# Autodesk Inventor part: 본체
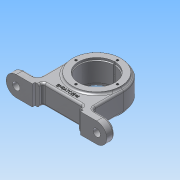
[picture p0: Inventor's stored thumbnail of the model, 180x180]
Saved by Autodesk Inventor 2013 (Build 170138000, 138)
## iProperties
Created: 2019-05
Part Number: 본체
Material: 알루미늄 6061
Document SubType Name: Modeling
Designer: Administrator
Density: 2.71 g/cm^3
Mass: 453.84 g
Surface Area: 319.447 cm^2
Volume: 167.468 cm^3
Author: Administrator
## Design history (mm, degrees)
sketch "스케치3"
  geometry: L1 (40, 4.967)-(40, -37.033); L2 (-40, -37.033)-(-40, 4.967); L3 (75, -43.033)-(75, -55.033); L4 (-75, -55.033)-(-75, -43.033); L5 (-75, -43.033)-(-46, -43.033); L6 (46, -43.033)-(75, -43.033); L7 (36, -51.033)-(36, -55.033); L8 (-36, -55.033)-(-36, -51.033); L9 (75, -55.033)-(36, -55.033); L10 (-36, -55.033)-(-75, -55.033); L11 (-30, -45.033)-(30, -45.033); L12 (30, -45.033)-(30, -51.033); L13 (-30, -51.033)-(-30, -45.033); L14 (-36, -51.033)-(-30, -51.033); L15 (30, -51.033)-(36, -51.033); C1 r 26 at (0, 4.967); A1 r 40 centre (0, 4.967) between (40, 4.967) and (-40, 4.967); A2 r 6 centre (-46, -37.033) between (-46, -43.033) and (-40, -37.033); A3 r 6 centre (46, -37.033) between (40, -37.033) and (46, -43.033); 3 further points
  constraints: 30 end point, 8 parallel, 6 point on circle, 5 horizontal, 5 perpendicular, 4 centre point, 4 tangent, 2 vertical alignment, 1 coincident, 1 equal radius, 1 horizontal alignment
  dimensions: "d12" = 80 diameter of A1; "d16" = 150 distance of L3.end L4.start; "d17" = 12 distance of L3.start L3.end; "d22" = 10 distance between parallel lines of L11 L10; "d23" = 4 distance between parallel lines of L10 L14; "d24" = 60 distance between parallel lines of L13 L12; "d25" = 72 distance between parallel lines of L7 L8; "d26" = 6 radius of A2; "d27" = 52 diameter of C1
extrude "돌출1" new body sketch "스케치3" distance "d28" = 15; taper "d30" = 0 deg; dims "d29" = 15, "d31" = 0
fillet "모깎기1" dims "d32" = 15
sketch "스케치4"
  geometry: C1 r 9 at (-14, 15); A1 r 15 centre (-14, 15) between (-14, 30) and (-14, 0) reference; 1 further point
  constraints: 1 centre point, 1 coincident
  dimensions: "d33" = 18 diameter of C1
extrude "돌출2" join sketch "스케치4" distance "d34" = 3; taper "d35" = 0 deg
hole "구멍1" diameter "d38" = 11; stored, may be unused: countersink angle "d42" = 90 deg, drill point angle "d44" = 118 deg; dims "d36" = 10, "d37" = 10, "d39" = 6, "d40" = 4, "d41" = 2, "d43" = 8
fillet "모깎기2" dims "d45" = 3
fillet "모깎기3" dims "d46" = 3
chamfer "모따기1" distance "d47" = 1; stored, may be unused: second distance "d48" = 2, angle "d49" = 45 deg
chamfer "모따기2" distance "d50" = 1; stored, may be unused: second distance "d51" = 2, angle "d52" = 45 deg
sketch "스케치5"
  geometry: C1 r 27 at (0, 4.967) reference; C2 r 36 at (0, 4.967); 1 further point
  constraints: 1 centre point, 1 coincident
  dimensions: "d53" = 72 diameter of C2
extrude "돌출3" join sketch "스케치5" distance "d54" = 3; taper "d55" = 0 deg
fillet "모깎기4" dims "d56" = 3
fillet "모깎기5" dims "d57" = 3
sketch "스케치6"
  geometry: L1 (0, 4.967)-(0, 35.967); L2 (0, 4.967)-(31, 4.967); A1 r 36 centre (0, 4.967) between (-34.154, -6.413) and (34.154, -6.413) reference; 1 further point
  constraints: 4 end point, 1 coincident, 1 horizontal, 1 perpendicular, 1 vertical
  dimensions: "d58" = 31 distance of L1.start L1.end; "d59" = 90 deg angle of L2 L1 (derived)
hole "구멍2" sketch "스케치6" at (0, 35.967) diameter "d60" = 3.459; stored, may be unused: countersink angle "d64" = 90 deg, drill point angle "d66" = 118 deg; dims "d61" = 6, "d62" = 4, "d63" = 2, "d65" = 8
fillet "모깎기6" dims "d70" = 3
sketch "스케치7"
  geometry: C1 r 1.5 at (0, 26); 2 further points
  constraints: 1 centre point, 1 vertical alignment, 1 other
  dimensions: "d71" = 3 diameter of C1
extrude "돌출4" cut sketch "스케치7" stored distance "d72" = 3; taper "d73" = 0 deg
node "작업 평면2"
sketch "스케치8"
  geometry: 1 further point
hole "구멍3" sketch "스케치8" at (0, 0) diameter "d74" = 4.917; stored, may be unused: countersink angle "d78" = 90 deg, drill point angle "d80" = 118 deg; dims "d75" = 8, "d76" = 7, "d77" = 1, "d79" = 10
sketch "스케치9"
  geometry: C1 r 1 at (0, 0); 1 further point
  constraints: 1 centre point, 1 coincident
  dimensions: "d81" = 2 diameter of C1
extrude "돌출5" cut sketch "스케치9" stored distance "d82" = 3; taper "d83" = 0 deg
sketch "스케치10"
  geometry: L1 (-27, -45.033)-(27, -45.033) reference; 4 further points
  constraints: 1 midpoint, 1 vertical alignment, 1 other
  dimensions: "d84" = 7 distance from line of L1 point (-16.708, -38.033)
feature "엠보싱1" sketch "스케치10" dims "d85" = 0.5, "d86" = 0
node "솔리드1"
mirror "대칭1"
mirror "대칭2"
pattern_circular "원형 패턴1" dims angle "d68" = 360 deg
mirror "대칭3"
